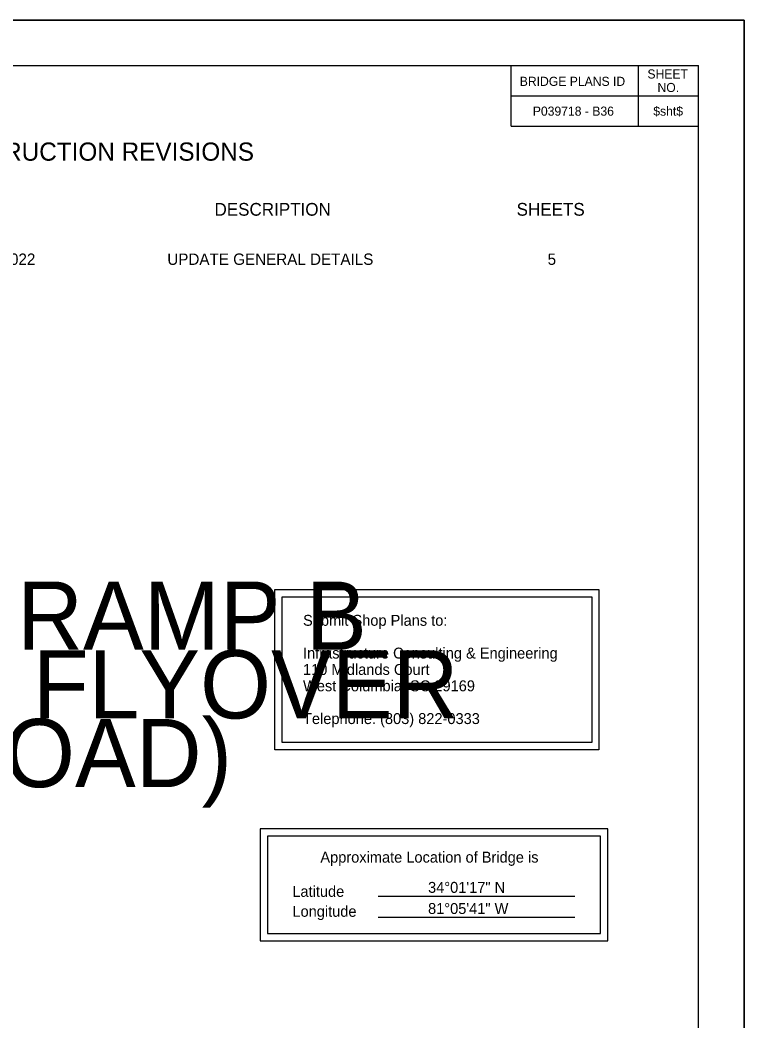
# Model space of a CAD drawing. Extents: x -1142 to 658, y -589 to 511.
# Drawn here: x 260 to 658, y -39 to 511 of the extents above; entities that cross this region are included whole.
import ezdxf

# ---------------------------------------------------------------- set-up
doc = ezdxf.new("R2010")
doc.units = 0
for name, color, linetype in [('BR_BORDER LINES', 7, 'Continuous'), ('BR_DETAILS', 7, 'Continuous'), ('BR_TEXT', 7, 'Continuous'), ('Default', 7, 'Continuous'), ('Level 31', 7, 'Continuous'), ('RD_SHT_IplotShp', 7, 'Continuous')]:
    doc.layers.add(name, color=color, linetype=linetype)

msp = doc.modelspace()

# ---------------------------------------------------------------- linework, layer by layer
at = {"layer": 'BR_BORDER LINES'}
for p, q in [((-1041.79, 485.67), (633.21, 485.67)), ((530.21, 452.33), (530.21, 485.67)), ((600.21, 452.33), (600.21, 485.67)), ((633.21, -564.26), (633.21, 485.67)), ((530.21, 469), (633.21, 469)), ((530.21, 452.33), (633.21, 452.33)), ((633.21, 427.4), (633.21, 452.27)), ((633.21, 75.01), (633.21, 427.47))]:
    msp.add_line(p, q, dxfattribs=at)
at = {"layer": 'Default'}
for p, q in [((457.1, 29.29), (565.24, 29.29)), ((457.1, 17.7), (565.24, 17.7))]:
    msp.add_line(p, q, dxfattribs=at)
for points in [[(400.22, 197.77), (578.44, 197.77), (578.44, 109.74), (400.22, 109.74)], [(404.22, 193.77), (574.44, 193.77), (574.44, 113.74), (404.22, 113.74)], [(583.24, 66.29), (392.18, 66.29), (392.18, 4.7), (583.24, 4.7)], [(579.24, 62.29), (396.18, 62.29), (396.18, 8.7), (579.24, 8.7)]]:
    msp.add_lwpolyline(points, close=True, dxfattribs=at)
at = {"layer": 'Level 31'}
msp.add_line((658.21, 510.67), (-1141.79, 510.67), dxfattribs=at)
msp.add_lwpolyline([(-1141.79, 510.67), (-1141.79, -589.33), (658.21, -589.33), (658.21, 510.67)], dxfattribs=at)
at = {"layer": 'RD_SHT_IplotShp'}
for p, q in [((-1141.79, 510.74), (658.21, 510.74)), ((658.21, 510.74), (658.21, -589.33))]:
    msp.add_line(p, q, dxfattribs=at)

# ---------------------------------------------------------------- texts
at = {"layer": 'BR_DETAILS'}
for s, height, p in [('BRIDGE PLANS ID', 5.0001, (534.89, 474.55)), ('SHEET', 5, (605.1, 478.6)), ('NO.', 5, (610.64, 471.16))]:
    msp.add_text(s, height=height, dxfattribs=at).set_placement(p)
at = {"layer": 'BR_TEXT'}
for s, p in [('P039718 - B36', (542.07, 458.17)), ('$sht$', (608.33, 458.17))]:
    msp.add_text(s, height=5, dxfattribs=at).set_placement(p)
at = {"layer": 'Default'}
for s, height, p in [('CONSTRUCTION REVISIONS', 9.9999, (204.5, 433.43)), ('DESCRIPTION', 7, (367.02, 403.21)), ('SHEETS', 7, (533.15, 403.21)), ('9/29/2022', 6.25, (231.31, 376.19)), ('UPDATE GENERAL DETAILS', 6.25, (341.06, 376.19)), ('5', 6.25, (550.21, 376.19)), ('ROAD S-2963 (COLONIAL LIFE BLVD.)  RAMP B', 37.5, (-669.53, 164.69)), ('Submit Shop Plans to:', 6, (415.7, 177.87)), ('Infrastructure Consulting & Engineering', 6, (415.7, 159.87)), ('BRIDGE OVER I-126, RAMP I-126 WB TO FLYOVER', 37.5, (-702.6, 126.94)), ('110 Midlands Court', 6, (415.7, 150.87)), ('West Columbia, SC 29169', 6, (415.7, 141.87)), ('AND ROAD S-287 (ARROWWOOD ROAD)', 37.5, (-595.71, 89.19)), ('Telephone: (803) 822-0333', 6, (415.7, 123.87)), ('Approximate Location of Bridge is', 6, (425.23, 47.73)), ('Latitude', 6, (409.82, 28.92)), ('34%%D01\'17" N', 6, (484.46, 31.12)), ('Longitude', 6, (409.87, 17.96)), ('81%%D05\'41" W', 6, (484.46, 19.5))]:
    msp.add_text(s, height=height, dxfattribs=at).set_placement(p)

doc.saveas('drawing.dxf')
